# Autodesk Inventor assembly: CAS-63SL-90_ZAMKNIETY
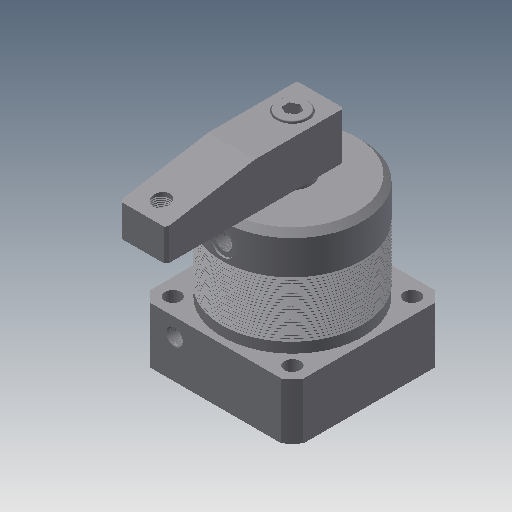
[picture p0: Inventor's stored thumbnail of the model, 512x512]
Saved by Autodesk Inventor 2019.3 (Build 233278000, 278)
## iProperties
Created: 2009-09
Part Number: CAS-63SL-90_ZAMKNIETY
Material: Ogólny
Document SubType Name: Assembly
Designer: CADENGINEERING4
Sending System: PRO/ENGINEER BY PARAMETRIC TECHNOLOGY CORPORATION, 2007170
Preprocessor: PRO/ENGINEER BY PARAMETRIC TECHNOLOGY CORPORATION, 2007170
Title: CAS-63S_ASM
Author: Administrator
Revision Number: 1LAST_VERSION
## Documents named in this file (7)
- D:\Vault_2016\Projekty\STRONA\Pneumatic\Line ; Pipe connecct - type\cas-63s_asm\CAS-63SL-90_ZAMKNIETY.iam
- D:\Vault_2016\Projekty\STRONA\Pneumatic\Line ; Pipe connecct - type\cas-63s_asm\CAS-63BT.ipt
- D:\Vault_2016\Projekty\STRONA\Pneumatic\Line ; Pipe connecct - type\cas-63s_asm\CAS-63SHSG.ipt
- D:\Vault_2016\Projekty\STRONA\Pneumatic\Line ; Pipe connecct - type\cas-63s_asm\CAS-63HG.ipt
- D:\Vault_2016\Projekty\STRONA\Pneumatic\Line ; Pipe connecct - type\cas-63s_asm\M4.ipt
- D:\Vault_2016\Projekty\STRONA\Pneumatic\Line ; Pipe connecct - type\cas-63s_asm\CAS-63SYB.ipt
- D:\Vault_2016\Projekty\STRONA\Pneumatic\Line ; Pipe connecct - type\cas-63s_asm\M10LC.ipt
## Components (11 placed, 11 different names)
1. CAS-63BT_0 — Zestawiające:5, Kątowe:1, Równoległe:1
2. CAS-63SHSG_1 — Zestawiające:1, Zestawiające:2, Zestawiające:4, Zestawiające:5
3. CAS-63HG_2
4. M4_3
5. M4_4
6. M4_5
7. M4_6
8. M4_7
9. M4_8
10. CAS-63SYB_9 — Zestawiające:1, Zestawiające:3, Zestawiające:4, Kątowe:1, Równoległe:1
11. M10LC_10 — Zestawiające:2, Zestawiające:3
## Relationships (7: Mate 5, Angle 1, Flush 1)
- Zestawiające:1 [Mate]: CAS-63SHSG_1 ↔ CAS-63SYB_9
- Zestawiające:2 [Mate]: CAS-63SHSG_1 ↔ M10LC_10
- Zestawiające:3 [Mate]: CAS-63SYB_9 ↔ M10LC_10
- Zestawiające:4 [Mate]: CAS-63SHSG_1 ↔ CAS-63SYB_9
- Zestawiające:5 [Mate]: CAS-63BT_0 ↔ CAS-63SHSG_1
- Kątowe:1 [Angle]: CAS-63BT_0 ↔ CAS-63SYB_9
- Równoległe:1 [Flush]: CAS-63BT_0 ↔ CAS-63SYB_9
